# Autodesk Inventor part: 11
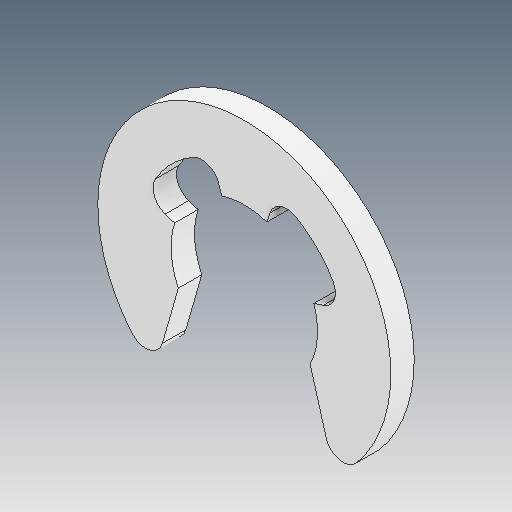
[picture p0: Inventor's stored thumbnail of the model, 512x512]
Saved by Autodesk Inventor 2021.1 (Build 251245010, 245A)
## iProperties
Created: 2021-06
Part Number: 11
Material: Ogólny
Document SubType Name: Modeling
Designer: user
Density: 1 g/cm^3
Appearance: Domyślna
Author: user
Revision Number: ÈÎºÎ
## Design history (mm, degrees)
feature "ÊäÈë1"
node "Bryła1"
